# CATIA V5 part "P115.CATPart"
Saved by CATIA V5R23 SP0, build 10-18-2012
Part number: P115
Definition: Palier lisse
Description: Palier lisse
Bounding box of the stored display mesh (mm): x 0 to 10, y -13 to 13, z -13 to 13
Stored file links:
  C:\wamp\www\COURS\CONCEPTION GMP1\TITRE 02-SEMESTRE 2\03-TP7-PRESSE MECANIQUE\eleve\P115.CATPart
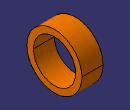
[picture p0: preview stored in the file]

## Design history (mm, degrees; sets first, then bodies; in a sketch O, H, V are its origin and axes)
Body1 (main body)
  Sketch1 on yz-plane, origin (0, 0, 0), H (0, 1, 0), V (0, 0, 1)
    circle A1 centre (0, 0) radius 13
    circle A2 centre (0, 0) radius 10
    radius A1 = 13
    radius A2 = 10
  Pad1: profile Sketch1, direction (1, 0, 0), length 10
